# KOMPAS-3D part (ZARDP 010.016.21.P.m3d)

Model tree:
1. Плоскость XY
2. Плоскость ZX
3. Плоскость ZY
4. Ось X
5. Ось Y
6. Ось Z
7. Начало координат
8. Смещенная плоскость:2
     Расстояние = 77.5
9. Булева операция:1
10. Булева операция:3
11. Булева операция:5
12. Булева операция:6
